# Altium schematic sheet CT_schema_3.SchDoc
size 328 x 327 mm
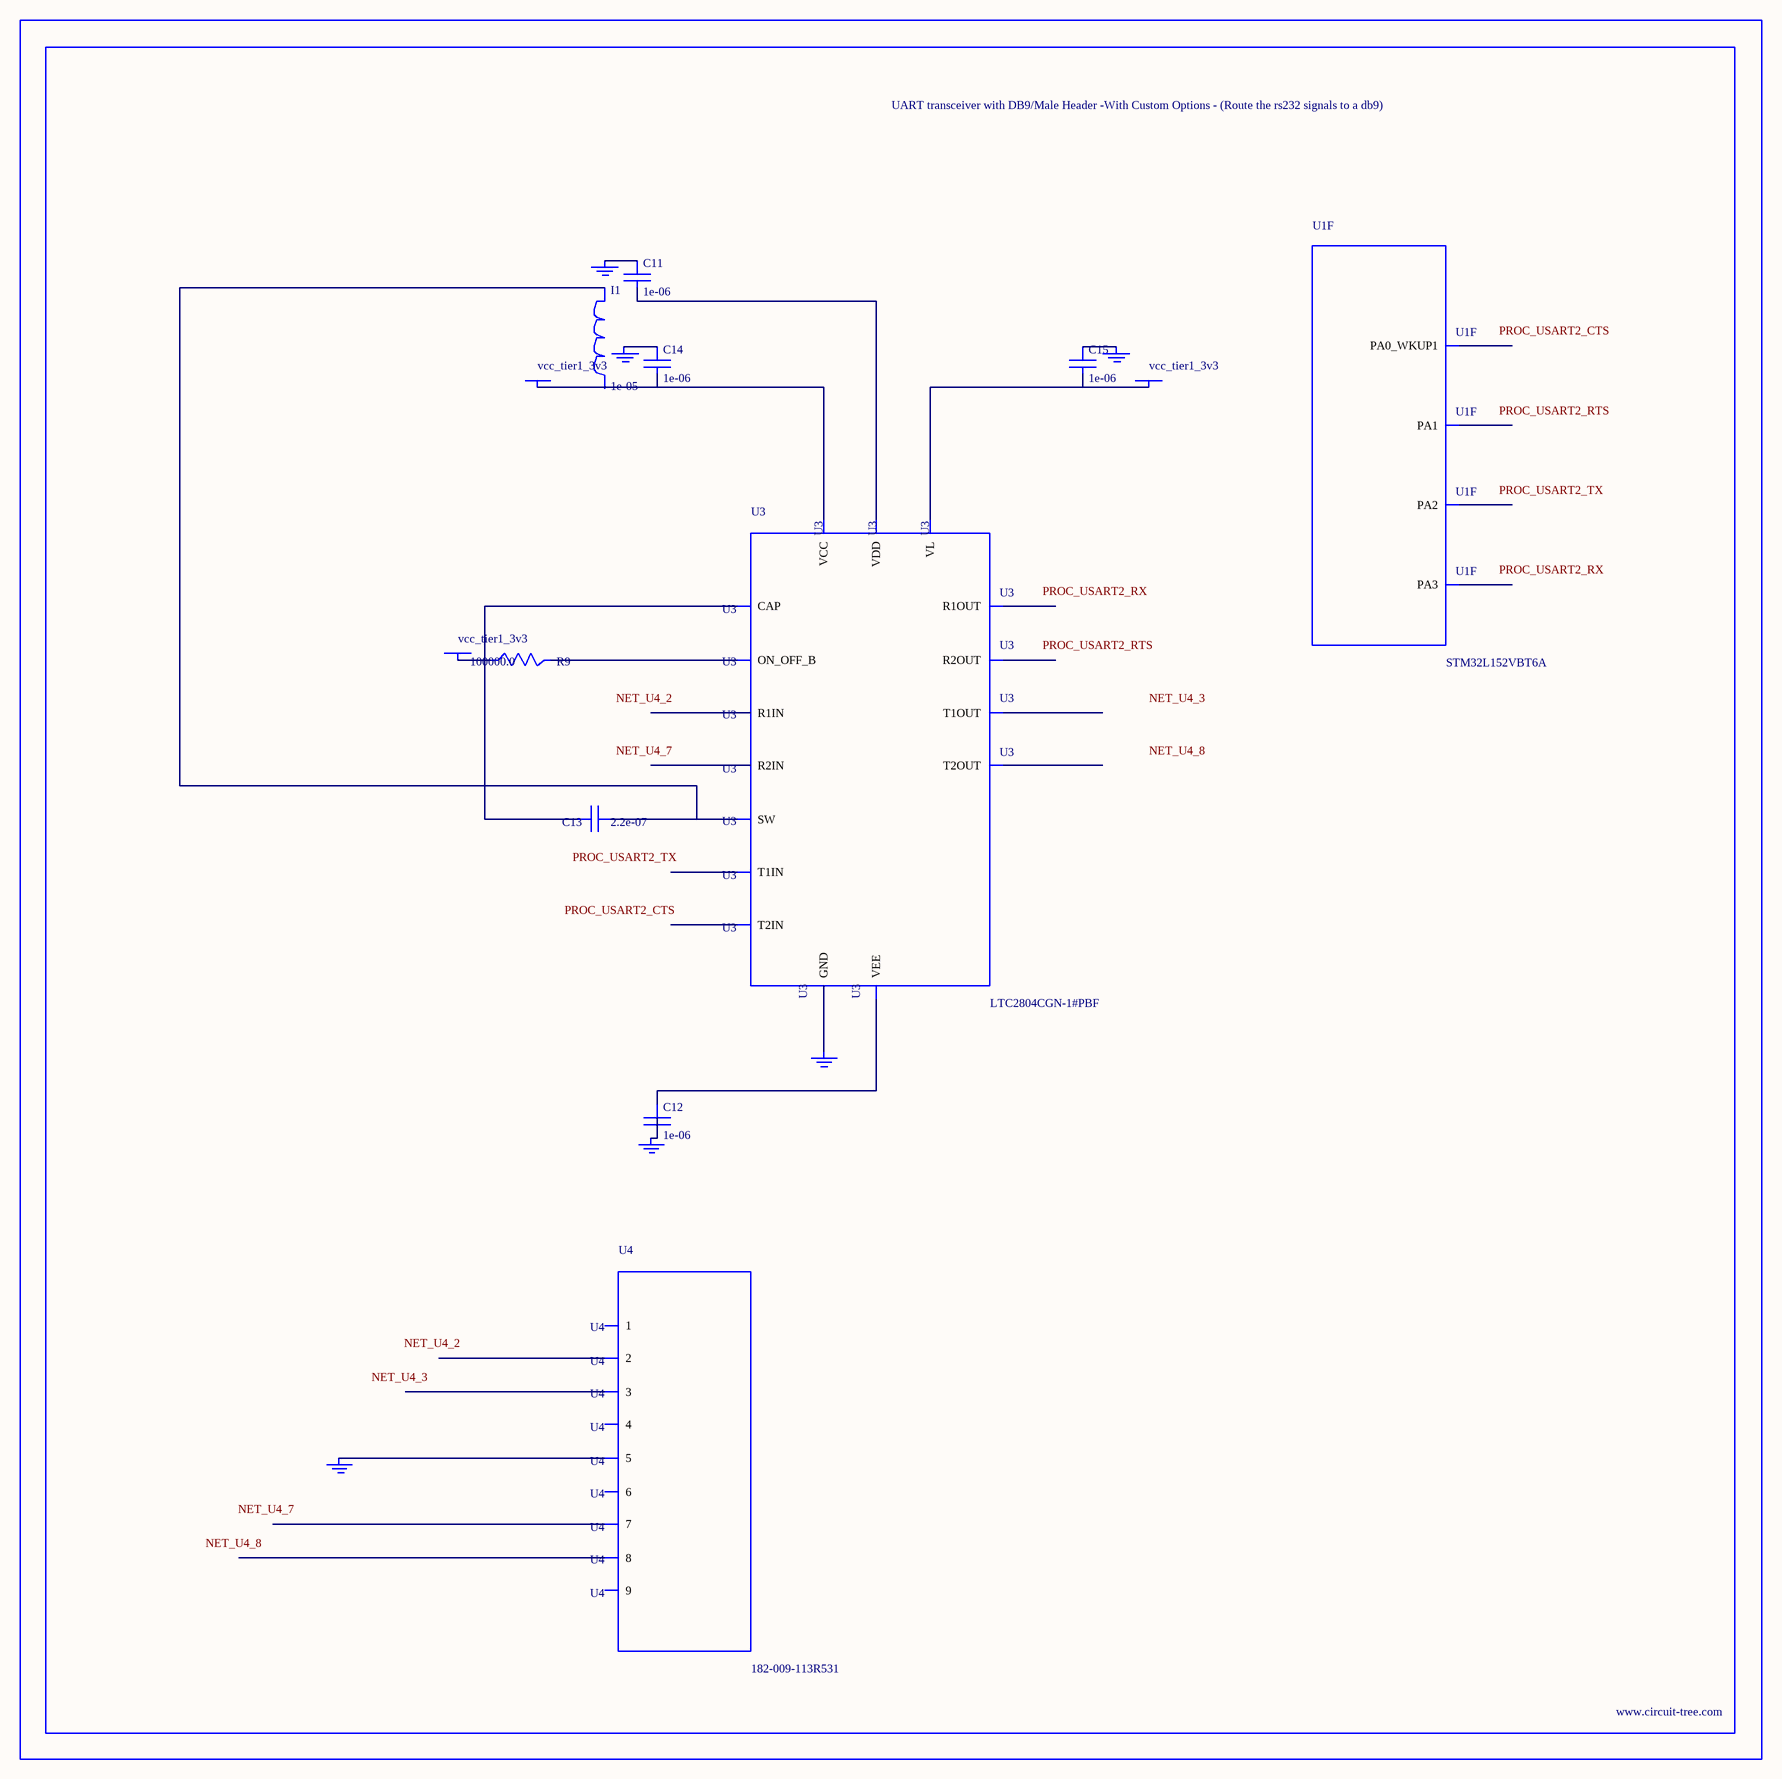
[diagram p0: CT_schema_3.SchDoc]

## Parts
BORDER2  (no value)
C11  1e-06  [C0603]
C12  1e-06  [C0603]
C13  2.2e-07  [C0603]
C14  1e-06  [C0603]
C15  1e-06  [C0603]
GND_INSTANCE_2_0  (no value)
GND_INSTANCE_2_1  (no value)
GND_INSTANCE_2_2  (no value)
GND_INSTANCE_2_3  (no value)
GND_INSTANCE_2_4  (no value)
GND_INSTANCE_2_5  (no value)
I1  1e-05  [L1210]
POWER_INSTANCE_2_0  vcc_tier1_3v3
POWER_INSTANCE_2_1  vcc_tier1_3v3
POWER_INSTANCE_2_2  vcc_tier1_3v3
R9  100000.0  [R0603]
U1  STM32L152VBT6A  [LQFP100]  (part F of 9)
U3  LTC2804CGN-1#PBF  [SSOP-16]
U4  182-009-113R531  [182-009-MALE]

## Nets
NetC11_1: C11.1 GND_INSTANCE_2_1.0(GND)
NetC11_2: C11.2 U3.6(VDD)
NetC12_1: C12.1 U3.9(VEE)
NetC12_2: C12.2 GND_INSTANCE_2_2.0(GND)
NetC13_1: C13.1 I1.1 U3.7(SW)
NetC13_2: C13.2 U3.10(CAP)
NetC14_1: C14.1 GND_INSTANCE_2_0.0(GND)
NetC14_2: C14.2 POWER_INSTANCE_2_0.0(PWR) U3.5(VCC)
NetC15_1: C15.1 GND_INSTANCE_2_3.0(GND)
NetC15_2: C15.2 POWER_INSTANCE_2_2.0(PWR) U3.12(VL)
NetGND_INSTANCE_2_4_0: GND_INSTANCE_2_4.0(GND) U3.8(GND)
NetGND_INSTANCE_2_5_0: GND_INSTANCE_2_5.0(GND) U4.5
NetPOWER_INSTANCE_2_1_0: POWER_INSTANCE_2_1.0(PWR) R9.1
NetR9_2: R9.2 U3.11(ON_OFF_B)

Not connected (* = marked no-connect by the designer): I1 2; U1 23(PA0_WKUP1) 24(PA1) 25(PA2) 26(PA3); U3 1(R1IN) 2(R2IN) 3(T1OUT) 4(T2OUT) 13(T2IN) 14(T1IN) 15(R2OUT) 16(R1OUT); U4 1 2 3 4 6 7 8 9

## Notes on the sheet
- Labels drawn without touching a wire or pin: NET_U4_2, NET_U4_3, NET_U4_7, NET_U4_8, PROC_USART2_CTS, PROC_USART2_RTS, PROC_USART2_RX, PROC_USART2_TX

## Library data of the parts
BORDER2 = BORDER_PAGE2
C11 C12 C14 C15 = C0603C105K3RACTU
C13 = C0603C224K3RAC
GND_INSTANCE_2_0-GND_INSTANCE_2_5 = GND
I1 = CBC3225T100MR
POWER_INSTANCE_2_0-POWER_INSTANCE_2_2 = PWR
R9 = RC0603JR-07100KL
